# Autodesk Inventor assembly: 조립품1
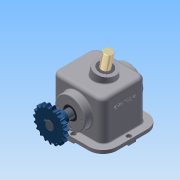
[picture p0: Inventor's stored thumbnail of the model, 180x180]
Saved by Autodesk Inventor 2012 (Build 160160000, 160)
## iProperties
Created: 2008-05
Part Number: 조립품1
Document SubType Name: Assembly
Designer: net1
Author: net1
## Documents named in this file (13)
- C:\Documents and Settings\net1\바탕 화면\441122V1012\조립품1.iam
- C:\Documents and Settings\net1\바탕 화면\441122V1012\본체.ipt
- C:\Documents and Settings\net1\바탕 화면\441122V1012\뒤커버.ipt
- C:\Documents and Settings\net1\바탕 화면\441122V1012\앞커버.ipt
- C:\Documents and Settings\net1\바탕 화면\441122V1012\베어링 6205.ipt
- C:\Documents and Settings\net1\바탕 화면\441122V1012\오일실.ipt
- C:\Documents and Settings\net1\바탕 화면\441122V1012\편심축.ipt
- C:\Documents and Settings\net1\바탕 화면\441122V1012\키 8x8.ipt
- C:\Documents and Settings\net1\바탕 화면\441122V1012\5-체인 스프로킷.ipt
- C:\Documents and Settings\net1\바탕 화면\441122V1012\슬라이드.ipt
- C:\Documents and Settings\net1\바탕 화면\441122V1012\부시.ipt
- C:\Documents and Settings\net1\바탕 화면\441122V1012\멈춤나사 M5x0.5.ipt
- C:\Documents and Settings\net1\바탕 화면\441122V1012\M4x0.5.ipt
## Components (9 placed, 2 different names)
1. 5-체인 스프로킷:1 — 각도:2
2. M4x0.5:1
3. M4x0.5:2
4. M4x0.5:3
5. M4x0.5:4
6. M4x0.5:5
7. M4x0.5:6
8. M4x0.5:7
9. M4x0.5:8
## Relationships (1: Angle 1)
- 각도:2 [Angle]: 5-체인 스프로킷:1
